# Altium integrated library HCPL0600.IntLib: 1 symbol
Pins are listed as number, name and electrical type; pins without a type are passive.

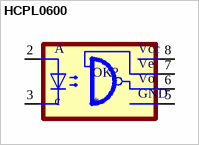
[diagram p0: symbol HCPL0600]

## HCPL0600
designator OK?
Logic Output Optoisolator 10MBd Open Collector, Schottky Clamped 3750Vrms 1 Channel 5kV/Âµs CMTI 8-SO Tall; MF: Broadcom Limited
footprint SOIC08
pins: 2 A, 3 C, 5 GND, 6 VO, 7 VE, 8 VCC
